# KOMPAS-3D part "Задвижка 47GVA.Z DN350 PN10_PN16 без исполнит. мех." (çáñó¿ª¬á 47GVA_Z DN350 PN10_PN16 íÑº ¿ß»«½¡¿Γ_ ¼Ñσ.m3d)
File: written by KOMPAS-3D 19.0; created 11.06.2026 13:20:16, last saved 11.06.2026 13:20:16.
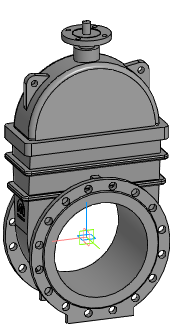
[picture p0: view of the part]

Document properties: Автор: Евгений; Полное имя файла: Z:\3.Личные\kachalov\001_3d для проектировщиков\2.2 Тип 47GVA, 47GVA.Z\_stp\_stp_Задвижка 47GVA.Z DN350-DN1200 без исп.мех\Задвижка 47GVA_Z DN350 PN10_PN16 без исполнит_ мех.m3d

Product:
- Part/product: Задвижка 47GVA.Z DN350 PN10_PN16 без исполнит. мех.

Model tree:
1. Операция без истории:1  (labels: Задвижка 47GVA.Z DN350 PN10_PN16 без исполнит. мех.)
